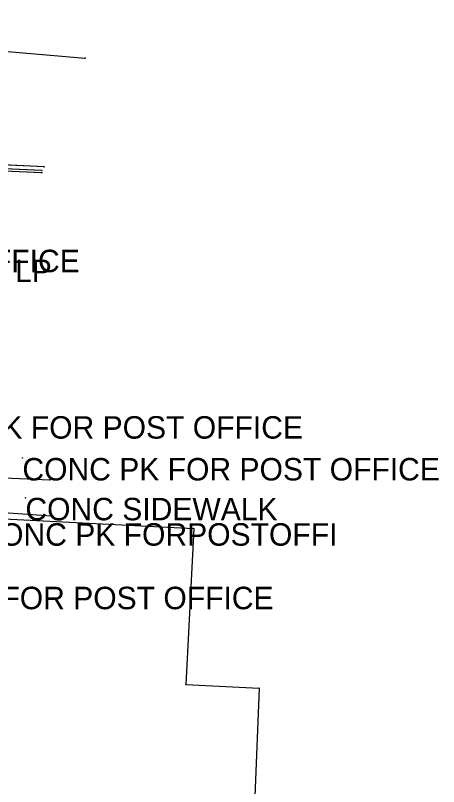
# Model space of a CAD drawing. Extents: x -99999 to 591807, y -99999 to 347168.
# Drawn here: x 591401.6 to 591495.7, y 320421.8 to 320593.4 of the extents above; entities that cross this region are included whole.
import ezdxf

# ---------------------------------------------------------------- set-up
doc = ezdxf.new("R2010")
doc.units = 0
for name, color, linetype in [('S_BREAKLINE', 7, 'Continuous'), ('S_BUILDING', 7, 'Continuous'), ('S_CURB', 7, 'Continuous'), ('S_EDGE_CONCRETE', 7, 'Continuous'), ('S_GRD_PT_SYM', 7, 'Continuous'), ('S_MSC_PT_SYM', 7, 'Continuous'), ('S_PARKING', 7, 'Continuous'), ('S_PRIMARY_CTL_ANNOT', 7, 'Continuous'), ('S_RDW_PT_SYM', 7, 'Continuous'), ('S_STR_PT_SYM', 7, 'Continuous'), ('S_SURVEY_TEXT_ANNOT', 7, 'Continuous')]:
    doc.layers.add(name, color=color, linetype=linetype)

msp = doc.modelspace()

# ---------------------------------------------------------------- linework, layer by layer
at = {"layer": 'S_BREAKLINE'}
for points in [[(591282.45, 320593.41), (591328.42, 320590.32), (591379.07, 320587.19), (591417.13, 320583.89)], [(591409.6, 320481.98), (591381.88, 320483.91)]]:
    msp.add_lwpolyline(points, dxfattribs=at)
at = {"layer": 'S_BUILDING'}
for p, q in [((591379.17, 320482.35), (591441.29, 320479.22)), ((591441.29, 320479.22), (591439.54, 320444.46)), ((591439.54, 320444.46), (591455.82, 320443.64)), ((591455.82, 320443.64), (591454.75, 320416.61))]:
    msp.add_line(p, q, dxfattribs=at)
at = {"layer": 'S_CURB'}
for points in [[(591407.48, 320558.41), (591363.84, 320560.32), (591322.91, 320562.3), (591285.89, 320563.97), (591281.19, 320567.39)], [(591407.48, 320558.41), (591385.66, 320559.37), (591363.84, 320560.32), (591343.38, 320561.31), (591322.91, 320562.3), (591304.4, 320563.13), (591285.89, 320563.97), (591281.19, 320567.39)], [(591407.5, 320558.91), (591363.86, 320560.82), (591322.94, 320562.8), (591286.07, 320564.46), (591281.48, 320567.8)], [(591407.5, 320558.91), (591385.68, 320559.87), (591363.86, 320560.82), (591343.4, 320561.81), (591322.94, 320562.8), (591304.5, 320563.63), (591286.07, 320564.46), (591281.48, 320567.8)], [(591407.5, 320558.91), (591363.86, 320560.82), (591322.94, 320562.8), (591286.07, 320564.46), (-99999, -99999)], [(591407.5, 320558.91), (591385.68, 320559.87), (591363.86, 320560.82), (591343.4, 320561.81), (591322.94, 320562.8), (591304.5, 320563.63), (591286.07, 320564.46)]]:
    msp.add_lwpolyline(points, dxfattribs=at)
at = {"layer": 'S_EDGE_CONCRETE'}
for points in [[(591350.2, 320440.33), (591351.92, 320476.5), (591352.97, 320500.54), (591339.73, 320501.19), (591337.73, 320501.84), (591336.14, 320503.31), (591335.37, 320505.22), (591335.59, 320507.9), (591336.94, 320509.96), (591338.91, 320511.12), (591340.36, 320511.28), (591361.85, 320510.23), (591363.69, 320509.44), (591365.36, 320507.73), (591365.85, 320506.13), (591365.58, 320496.92), (591365.34, 320491.96), (591409.25, 320490.03)], [(591350.2, 320440.33), (591351.06, 320458.41), (591351.92, 320476.5), (591352.97, 320500.54), (591339.73, 320501.19), (591337.73, 320501.84), (591336.14, 320503.31), (591335.37, 320505.22), (591335.59, 320507.9), (591336.94, 320509.96), (591338.91, 320511.12), (591340.36, 320511.28), (591361.85, 320510.23), (591363.69, 320509.44), (591365.36, 320507.73), (591365.85, 320506.13), (591365.58, 320496.92), (591365.34, 320491.96), (591387.3, 320491), (591409.25, 320490.03)]]:
    msp.add_lwpolyline(points, dxfattribs=at)
at = {"layer": 'S_GRD_PT_SYM'}
for points in [[(591417.13, 320583.89), (591417.14, 320583.94), (591417.13, 320583.89), (591417.08, 320583.89), (591417.13, 320583.89), (591417.13, 320583.84), (591417.13, 320583.89), (591417.18, 320583.88)], [(591409.6, 320481.98), (591409.6, 320481.93), (591409.6, 320481.98), (591409.65, 320481.98), (591409.6, 320481.98), (591409.6, 320482.03), (591409.6, 320481.98), (591409.55, 320481.99)]]:
    msp.add_lwpolyline(points, close=True, dxfattribs=at)
at = {"layer": 'S_MSC_PT_SYM'}
for points in [[(591407.98, 320559.72), (591407.98, 320559.67), (591407.98, 320559.72), (591408.03, 320559.72), (591407.98, 320559.72), (591407.98, 320559.77), (591407.98, 320559.72), (591407.93, 320559.72)], [(591409.25, 320490.04), (591409.26, 320490.09), (591409.25, 320490.04), (591409.2, 320490.04), (591409.25, 320490.04), (591409.25, 320489.99), (591409.25, 320490.04), (591409.3, 320490.03)]]:
    msp.add_lwpolyline(points, close=True, dxfattribs=at)
for points in [[(591403.16, 320494.9), (591403.16, 320494.95), (591403.16, 320494.9), (591403.11, 320494.9), (591403.16, 320494.9), (591403.16, 320494.85), (591403.16, 320494.9), (591403.21, 320494.9)], [(591403.83, 320486.03), (591403.83, 320486.08), (591403.83, 320486.03), (591403.78, 320486.03), (591403.83, 320486.03), (591403.83, 320485.98), (591403.83, 320486.03), (591403.88, 320486.03)]]:
    msp.add_lwpolyline(points, dxfattribs=at)
at = {"layer": 'S_PARKING'}
for points in [[(591407.98, 320559.72), (591364.01, 320561.85), (591322.95, 320563.71), (591286.43, 320565.42), (591275.45, 320573.33)], [(591407.98, 320559.72), (591385.99, 320560.78), (591364.01, 320561.85), (591343.48, 320562.78), (591322.95, 320563.71), (591304.69, 320564.56), (591286.43, 320565.42), (591275.45, 320573.33)], [(591350.2, 320440.33), (591351.92, 320476.5), (591352.97, 320500.54), (591339.73, 320501.19), (591337.73, 320501.84), (591336.14, 320503.31), (591335.37, 320505.22), (591335.59, 320507.9), (591336.94, 320509.96), (591338.91, 320511.12), (591340.36, 320511.28), (591361.85, 320510.23), (591363.69, 320509.45), (591365.36, 320507.73), (591365.85, 320506.13), (591365.58, 320496.92), (591365.34, 320491.97), (591409.25, 320490.04)], [(591350.2, 320440.33), (591351.06, 320458.41), (591351.92, 320476.5), (591352.97, 320500.54), (591339.73, 320501.19), (591337.73, 320501.84), (591336.14, 320503.31), (591335.37, 320505.22), (591335.59, 320507.9), (591336.94, 320509.96), (591338.91, 320511.12), (591340.36, 320511.28), (591361.85, 320510.23), (591363.69, 320509.45), (591365.36, 320507.73), (591365.85, 320506.13), (591365.58, 320496.92), (591365.34, 320491.97), (591387.3, 320491), (591409.25, 320490.04)]]:
    msp.add_lwpolyline(points, dxfattribs=at)
at = {"layer": 'S_RDW_PT_SYM'}
for points in [[(591407.48, 320558.41), (591407.48, 320558.36), (591407.48, 320558.41), (591407.53, 320558.41), (591407.48, 320558.41), (591407.48, 320558.46), (591407.48, 320558.41), (591407.43, 320558.41)], [(591407.5, 320558.91), (591407.5, 320558.96), (591407.5, 320558.91), (591407.45, 320558.91), (591407.5, 320558.91), (591407.5, 320558.86), (591407.5, 320558.91), (591407.55, 320558.91)], [(591407.5, 320558.91), (591407.5, 320558.86), (591407.5, 320558.91), (591407.55, 320558.91), (591407.5, 320558.91), (591407.5, 320558.96), (591407.5, 320558.91), (591407.45, 320558.91)], [(591407.5, 320558.91), (591407.5, 320558.86), (591407.5, 320558.91), (591407.55, 320558.91), (591407.5, 320558.91), (591407.5, 320558.96), (591407.5, 320558.91), (591407.45, 320558.91)], [(591409.25, 320490.03), (591409.26, 320490.08), (591409.25, 320490.03), (591409.2, 320490.04), (591409.25, 320490.03), (591409.25, 320489.98), (591409.25, 320490.03), (591409.3, 320490.03)]]:
    msp.add_lwpolyline(points, close=True, dxfattribs=at)
at = {"layer": 'S_STR_PT_SYM'}
for points in [[(591441.29, 320479.22), (591441.29, 320479.27), (591441.29, 320479.22), (591441.24, 320479.22), (591441.29, 320479.22), (591441.29, 320479.17), (591441.29, 320479.22), (591441.34, 320479.22)], [(591439.54, 320444.46), (591439.54, 320444.51), (591439.54, 320444.46), (591439.49, 320444.46), (591439.54, 320444.46), (591439.54, 320444.41), (591439.54, 320444.46), (591439.59, 320444.46)], [(591455.82, 320443.64), (591455.82, 320443.69), (591455.82, 320443.64), (591455.77, 320443.64), (591455.82, 320443.64), (591455.82, 320443.59), (591455.82, 320443.64), (591455.87, 320443.64)]]:
    msp.add_lwpolyline(points, dxfattribs=at)

# ---------------------------------------------------------------- texts
at = {"layer": 'S_PRIMARY_CTL_ANNOT'}
msp.add_text('PD:SQ CUT CONCRETE BASE LP', height=5, dxfattribs=at).set_placement((591304.19, 320534.07))
at = {"layer": 'S_SURVEY_TEXT_ANNOT'}
for s, p in [('CONC PK TO POST OFFICE', (591327.88, 320536.26)), ('CONC PK FOR POST OFFICE', (591372.71, 320499.21)), ('CONC PK FOR POST OFFICE', (591403.16, 320489.9)), ('CONC SIDEWALK', (591403.83, 320481.03)), ('CONC PK FOR CONC PK FORPOSTOFFI', (591345.08, 320475.38)), ('CONC PAD FOR POST OFFICE', (591361.34, 320461.24))]:
    msp.add_text(s, height=5, dxfattribs=at).set_placement(p)

doc.saveas('drawing.dxf')
